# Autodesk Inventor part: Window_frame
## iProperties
Shininess: 64.0
Length Units: 11269
Angle Units: 11279
Time Units: 11290
Mass Units: 11283
Length Display Precision: 3
Angle Display Precision: 2
Compacted: True
Part Number: Window_frame
Document SubType Name: Modeling
Created: 2003-02
Material: Standard
Designer: hofer_a
Density: 0.0
Volumn: 0.0
Area: 0.0
PropertySet Name: Model Information
Control State: 0
Master: False
Checked Out: False
Author: hofer_a
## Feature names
1. Extrusion1
2. Bohrung1 [Hole]
3. Extrusion2
4. Extrusion4
5. Rundung1 [Fillet]
6. Extrusion5
7. Extrusion6
8. Extrusion7
9. Bohrung3 [Hole]
10. Bohrung4 [Hole]
